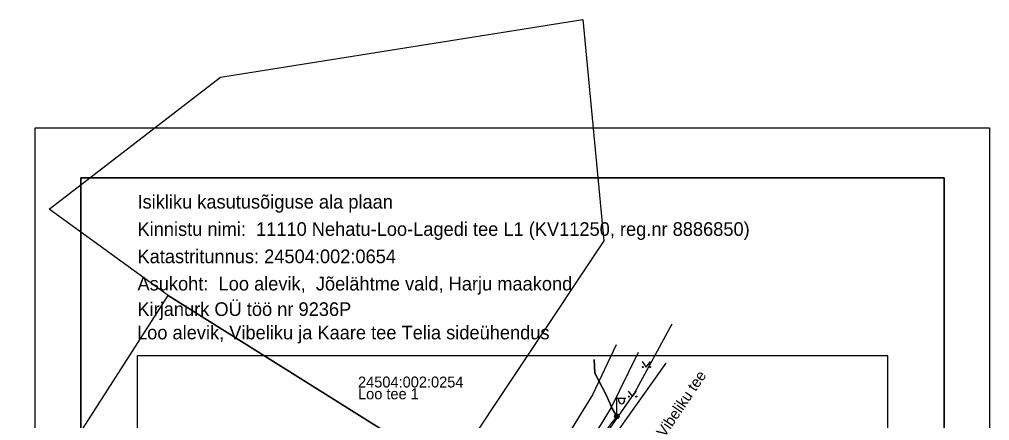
# Model space of a CAD drawing. Extents: x 553261 to 553443, y 6588794 to 6589074.
# Drawn here: x 553336.5 to 553443.3, y 6589029.9 to 6589073.9 of the extents above; entities that cross this region are included whole.
import ezdxf

# ---------------------------------------------------------------- set-up
doc = ezdxf.new("R2010")
doc.units = 0
for name, color, linetype in [('HALJASTUS', 7, 'Continuous'), ('MPKAABEL', 7, 'Continuous'), ('PIIR', 7, 'Continuous'), ('POST', 7, 'Continuous'), ('TEE', 7, 'Continuous'), ('VORMISTUS_1', 7, 'Continuous')]:
    doc.layers.add(name, color=color, linetype=linetype)

msp = doc.modelspace()

# ---------------------------------------------------------------- linework, layer by layer
at = {"layer": 'HALJASTUS'}
for p, q in [((553405.03, 6589036.36), (553405.49, 6589035.76)), ((553405.49, 6589035.76), (553405.94, 6589036.36)), ((553403.5, 6589033.12), (553403.96, 6589032.51)), ((553403.96, 6589032.51), (553404.41, 6589033.12))]:
    msp.add_line(p, q, dxfattribs=at)
for centre in [(553405.09, 6589035.76), (553405.92, 6589035.76), (553403.56, 6589032.51), (553404.39, 6589032.51)]:
    msp.add_circle(centre, 0.055, dxfattribs=at)
at = {"layer": 'MPKAABEL'}
for points in [[(553402.26, 6589030.33), (553401.75, 6589031.2), (553401.06, 6589032.71), (553399.82, 6589035.07), (553399.74, 6589036.59)], [(553399.74, 6589036.59), (553399.82, 6589035.07), (553401.06, 6589032.71), (553401.75, 6589031.2), (553402.26, 6589030.33)], [(553402.26, 6589030.33), (553401.56, 6589029.49), (553392.54, 6589016.41), (553389.65, 6589012.12), (553381.74, 6589000.9), (553380.21, 6588999.02), (553379.22, 6588997.23), (553369.04, 6588982.57), (553359.56, 6588969.42), (553358.78, 6588968.31), (553357.88, 6588967.14), (553354.21, 6588961.74), (553348.52, 6588953.58)], [(553402.26, 6589030.33), (553401.56, 6589029.49), (553392.54, 6589016.41), (553389.65, 6589012.12), (553381.74, 6589000.9), (553380.21, 6588999.02), (553379.22, 6588997.23), (553369.04, 6588982.57), (553359.56, 6588969.42), (553358.78, 6588968.31), (553357.88, 6588967.14), (553354.21, 6588961.74), (553348.52, 6588953.58)]]:
    msp.add_lwpolyline(points, dxfattribs=at)
at = {"layer": 'PIIR'}
for points in [[(553398.49, 6589073.95), (553400.8, 6589049.61), (553383.89, 6589024.22), (553352.89, 6589043.6), (553339.8, 6589053.09), (553358.63, 6589067.61)], [(553352.89, 6589043.6), (553383.89, 6589024.22), (553353.8, 6588979.04), (553322.14, 6588995.79)]]:
    msp.add_lwpolyline(points, close=True, dxfattribs=at)
msp.add_lwpolyline([(553269.61, 6588823.39), (553275.1, 6588838.43), (553306.34, 6588891.77), (553312.93, 6588901.87), (553404.2, 6589032.89), (553408.34, 6589040.49)], dxfattribs=at)
at = {"layer": 'POST'}
for p, q in [((553402.24, 6589030.59), (553402.24, 6589032.59)), ((553402.24, 6589032.34), (553403.24, 6589032.34)), ((553402.47, 6589032.02), (553402.47, 6589032.34)), ((553403.08, 6589032.02), (553403.08, 6589032.34)), ((553402.24, 6589030.34), (553402.24, 6589030.34))]:
    msp.add_line(p, q, dxfattribs=at)
for radius in [0.25, 0.225, 0.2, 0.175, 0.15, 0.125, 0.1, 0.075, 0.05, 0.025]:
    msp.add_circle((553402.24, 6589030.34), radius, dxfattribs=at)
msp.add_arc((553402.78, 6589032.02), 0.306, 180, 0, dxfattribs=at)
at = {"layer": 'TEE'}
for points in [[(553402.19, 6589038.21), (553399.57, 6589032.71), (553396.55, 6589027.84), (553387.86, 6589015.45), (553386.93, 6589016.25)], [(553407.63, 6589036.2), (553403.14, 6589029.86), (553400.1, 6589025.56), (553392.6, 6589014.64), (553390.44, 6589014.59), (553398.69, 6589026.47), (553401.56, 6589031.12), (553404.62, 6589037.38)]]:
    msp.add_lwpolyline(points, dxfattribs=at)
at = {"layer": 'VORMISTUS_1'}
for points in [[(553338.26, 6589062.04), (553443.26, 6589062.04), (553443.26, 6588913.54), (553338.26, 6588913.54)], [(553343.26, 6588919.04), (553438.26, 6588919.04), (553438.26, 6589056.54), (553343.26, 6589056.54)], [(553343.26, 6589056.54), (553438.26, 6589056.54), (553438.26, 6588919.04), (553343.26, 6588919.04)], [(553432.01, 6588932.04), (553349.51, 6588932.04), (553349.51, 6589037.04), (553432.01, 6589037.04)]]:
    msp.add_lwpolyline(points, close=True, dxfattribs=at)

# ---------------------------------------------------------------- texts
at = {"layer": 'PIIR'}
for s, p in [('24504:002:0254', (553373.77, 6589033.51)), ('Loo tee 1', (553373.77, 6589032.21))]:
    msp.add_text(s, height=1.2, dxfattribs=at).set_placement(p)
at = {"layer": 'TEE'}
msp.add_text('Vibeliku tee', height=1.2, rotation=56.0611, dxfattribs=at).set_placement((553407.52, 6589027.96))
at = {"layer": 'VORMISTUS_1'}
for s, p in [('Isikliku kasutusõiguse ala plaan', (553349.51, 6589053.17)), ('Kinnistu nimi:  11110 Nehatu-Loo-Lagedi tee L1 (KV11250, reg.nr 8886850)', (553349.51, 6589050.17)), ('Katastritunnus: 24504:002:0654', (553349.51, 6589047.17)), ('Asukoht:  Loo alevik,  Jõelähtme vald, Harju maakond', (553349.51, 6589044.17))]:
    msp.add_text(s, height=1.5, dxfattribs=at).set_placement(p)
for s, p in [('Kirjanurk OÜ töö nr 9236P', (553349.5, 6589041.37)), ('Loo alevik, Vibeliku ja Kaare tee Telia sideühendus', (553349.46, 6589038.8))]:
    msp.add_text(s, height=1.5, rotation=360, dxfattribs=at).set_placement(p)

doc.saveas('drawing.dxf')
